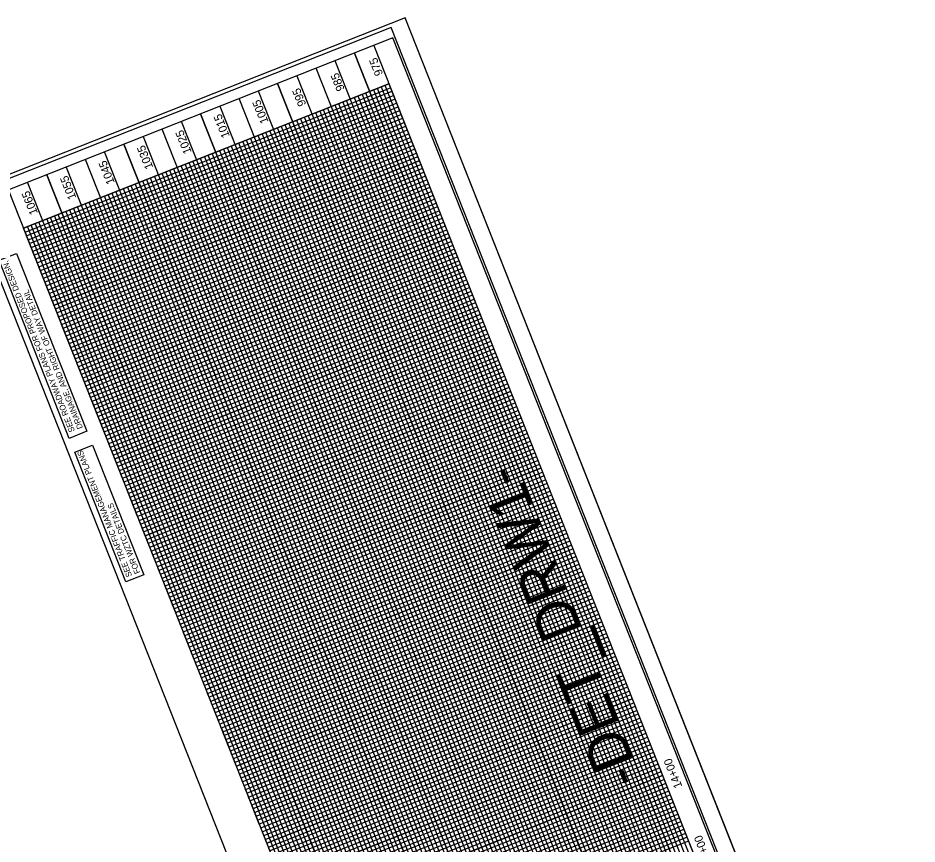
# Model space of a CAD drawing. Extents: x 1250120 to 1251758, y 748130 to 750098.
# Drawn here: x 1250670 to 1251758, y 749099 to 750098 of the extents above; entities that cross this region are included whole.
import ezdxf

# ---------------------------------------------------------------- set-up
doc = ezdxf.new("R2010")
doc.units = 0
for name, color, linetype in [('Exist Vertical Profile Horizontal Axis Label Major', 7, 'Continuous'), ('Exist Vertical Profile Vertical Axis Label', 7, 'Continuous'), ('Prop Grid Mask', 7, 'Continuous'), ('Prop PFL Text', 7, 'Continuous'), ('Sheet Cutting Line CELL', 7, 'Continuous'), ('Sheet Data Field CELL', 7, 'Continuous'), ('Sheet DOT Grid CELL', 7, 'Continuous'), ('Sheet Layout Plan Border', 7, 'Continuous'), ('Sheet Layout Profile Border Port 2', 7, 'Continuous'), ('Sheet Plan And Profile CELL', 7, 'Continuous'), ('Sheet Plot Border Inside CELL', 7, 'Continuous'), ('Sheet Plot Border Outside CELL', 7, 'Continuous'), ('Sheet Profile Grid Major CELL', 7, 'Continuous'), ('Sheet Profile Grid Middle CELL', 7, 'Continuous'), ('Sheet Profile Grid Minor CELL', 7, 'Continuous')]:
    doc.layers.add(name, color=color, linetype=linetype)

msp = doc.modelspace()

# ---------------------------------------------------------------- linework, layer by layer
at = {"layer": 'Prop Grid Mask'}
for points in [[(1250732.4, 749589.4), (1250647.3, 749804.8), (1250668.7, 749813.2), (1250753.8, 749597.9)], [(1250801.1, 749415.8), (1250739.1, 749572.6), (1250760.5, 749581), (1250822.5, 749424.3)]]:
    msp.add_lwpolyline(points, close=True, dxfattribs=at)
at = {"layer": 'Sheet Cutting Line CELL'}
msp.add_line((1251757.6, 748532.4), (1251138.6, 750098), dxfattribs=at)
at = {"layer": 'Sheet DOT Grid CELL'}
for p, q in [((1251629, 748660.6), (1251077.4, 750055.5)), ((1251582.5, 748642.2), (1251030.9, 750037.1)), ((1250677.3, 749843.5), (1251119.1, 750018.2)), ((1251536, 748623.8), (1250984.4, 750018.7)), ((1251489.5, 748605.4), (1250937.9, 750000.4)), ((1251443, 748587.1), (1250891.4, 749982)), ((1250695.7, 749797.1), (1251137.5, 749971.7)), ((1251396.5, 748568.7), (1250844.9, 749963.6)), ((1251350, 748550.3), (1250798.5, 749945.2)), ((1250714.1, 749750.6), (1251155.8, 749925.2)), ((1251303.5, 748531.9), (1250752, 749926.8)), ((1251257, 748513.5), (1250705.5, 749908.4)), ((1251210.5, 748495.1), (1250659, 749890)), ((1250732.5, 749704.1), (1251174.2, 749878.7)), ((1250750.9, 749657.6), (1251192.6, 749832.2)), ((1250769.3, 749611.1), (1251211, 749785.7)), ((1250787.7, 749564.6), (1251229.4, 749739.2)), ((1250806, 749518.1), (1251247.8, 749692.7)), ((1250824.4, 749471.6), (1251266.1, 749646.2)), ((1250842.8, 749425.1), (1251284.5, 749599.7)), ((1250861.2, 749378.6), (1251302.9, 749553.2)), ((1250879.6, 749332.1), (1251321.3, 749506.7)), ((1250898, 749285.6), (1251339.7, 749460.2)), ((1250916.4, 749239.1), (1251358.1, 749413.7)), ((1250934.7, 749192.6), (1251376.5, 749367.3)), ((1250953.1, 749146.1), (1251394.8, 749320.8)), ((1250971.5, 749099.6), (1251413.2, 749274.3)), ((1250989.9, 749053.1), (1251431.6, 749227.8)), ((1251008.3, 749006.6), (1251450, 749181.3)), ((1251026.7, 748960.1), (1251468.4, 749134.8))]:
    msp.add_line(p, q, dxfattribs=at)
at = {"layer": 'Sheet Layout Plan Border'}
msp.add_lwpolyline([(1251145.6, 748523.2), (1250727.2, 748357.8), (1250285.9, 749473.7), (1250436.1, 749533), (1250362.5, 749719.1), (1250630.8, 749825.2)], close=True, dxfattribs=at)
at = {"layer": 'Sheet Layout Profile Border Port 2'}
msp.add_lwpolyline([(1251192.1, 748541.6), (1250677.3, 749843.5), (1251119.1, 750018.2), (1251633.9, 748716.3)], close=True, dxfattribs=at)
at = {"layer": 'Sheet Plan And Profile CELL'}
msp.add_line((1251100.7, 750064.7), (1251652.2, 748669.8), dxfattribs=at)
msp.add_lwpolyline([(1250147.5, 749687.8), (1250699.1, 748292.9), (1251675.5, 748679), (1251123.9, 750073.9)], close=True, dxfattribs=at)
at = {"layer": 'Sheet Plot Border Inside CELL'}
msp.add_lwpolyline([(1251734.3, 748537.2), (1251121.7, 750086.4), (1250140.6, 749698.5), (1250753.2, 748149.2)], close=True, dxfattribs=at)
at = {"layer": 'Sheet Plot Border Outside CELL'}
msp.add_lwpolyline([(1251757.6, 748532.4), (1251138.6, 750098), (1250120.3, 749695.3), (1250739.4, 748129.8)], close=True, dxfattribs=at)
at = {"layer": 'Sheet Profile Grid Major CELL'}
for points in [[(1251077.4, 750055.5), (1251629, 748660.6)], [(1250984.4, 750018.7), (1251536, 748623.8), (1251582.5, 748642.2), (1251030.9, 750037.1)], [(1251119.1, 750018.2), (1250677.3, 749843.5)], [(1250891.4, 749982), (1251443, 748587.1), (1251489.5, 748605.4), (1250937.9, 750000.4)], [(1251155.8, 749925.2), (1250714.1, 749750.6), (1250695.7, 749797.1), (1251137.5, 749971.7)], [(1250798.5, 749945.2), (1251350, 748550.3), (1251396.5, 748568.7), (1250844.9, 749963.6)], [(1250705.5, 749908.4), (1251257, 748513.5), (1251303.5, 748531.9), (1250752, 749926.8)], [(1251210.5, 748495.1), (1250659, 749890)], [(1251192.6, 749832.2), (1250750.9, 749657.6), (1250732.5, 749704.1), (1251174.2, 749878.7)], [(1251229.4, 749739.2), (1250787.7, 749564.6), (1250769.3, 749611.1), (1251211, 749785.7)], [(1251266.1, 749646.2), (1250824.4, 749471.6), (1250806, 749518.1), (1251247.8, 749692.7)], [(1251302.9, 749553.2), (1250861.2, 749378.6), (1250842.8, 749425.1), (1251284.5, 749599.7)], [(1251339.7, 749460.2), (1250898, 749285.6), (1250879.6, 749332.1), (1251321.3, 749506.7)], [(1251376.5, 749367.3), (1250934.7, 749192.6), (1250916.4, 749239.1), (1251358.1, 749413.7)], [(1251413.2, 749274.3), (1250971.5, 749099.6), (1250953.1, 749146.1), (1251394.8, 749320.8)], [(1251450, 749181.3), (1251008.3, 749006.6), (1250989.9, 749053.1), (1251431.6, 749227.8)], [(1251486.8, 749088.3), (1251045.1, 748913.6), (1251026.7, 748960.1), (1251468.4, 749134.8)]]:
    msp.add_lwpolyline(points, dxfattribs=at)
at = {"layer": 'Sheet Profile Grid Middle CELL'}
for p, q in [((1251605.7, 748651.4), (1251054.2, 750046.3)), ((1251007.7, 750027.9), (1251559.2, 748633)), ((1251512.8, 748614.6), (1250961.2, 750009.6)), ((1250914.7, 749991.2), (1251466.3, 748596.3)), ((1251419.8, 748577.9), (1250868.2, 749972.8)), ((1250821.7, 749954.4), (1251373.3, 748559.5)), ((1251326.8, 748541.1), (1250775.2, 749936)), ((1250728.7, 749917.6), (1251280.3, 748522.7)), ((1251233.8, 748504.3), (1250682.2, 749899.2))]:
    msp.add_line(p, q, dxfattribs=at)
for points in [[(1251146.6, 749948.5), (1250704.9, 749773.8), (1250686.5, 749820.3), (1251128.3, 749995)], [(1251183.4, 749855.5), (1250741.7, 749680.8), (1250723.3, 749727.3), (1251165, 749902)], [(1251220.2, 749762.5), (1250778.5, 749587.8), (1250760.1, 749634.3), (1251201.8, 749809)], [(1251257, 749669.5), (1250815.2, 749494.8), (1250796.8, 749541.3), (1251238.6, 749716)], [(1251293.7, 749576.5), (1250852, 749401.8), (1250833.6, 749448.3), (1251275.3, 749623)], [(1251330.5, 749483.5), (1250888.8, 749308.8), (1250870.4, 749355.3), (1251312.1, 749530)], [(1251367.3, 749390.5), (1250925.5, 749215.8), (1250907.2, 749262.3), (1251348.9, 749437)], [(1251404, 749297.5), (1250962.3, 749122.8), (1250943.9, 749169.3), (1251385.7, 749344)], [(1251440.8, 749204.5), (1250999.1, 749029.9), (1250980.7, 749076.3), (1251422.4, 749251)], [(1251477.6, 749111.5), (1251035.9, 748936.9), (1251017.5, 748983.4), (1251459.2, 749158)]]:
    msp.add_lwpolyline(points, dxfattribs=at)
at = {"layer": 'Sheet Profile Grid Minor CELL'}
for points in [[(1251122.7, 750008.9), (1250681, 749834.3), (1250679.2, 749838.9), (1251120.9, 750013.6)], [(1251629.2, 748714.5), (1251114.4, 750016.4), (1251109.8, 750014.5), (1251624.6, 748712.6), (1251619.9, 748710.8), (1251105.1, 750012.7), (1251100.5, 750010.9), (1251615.3, 748708.9), (1251610.6, 748707.1), (1251606, 748705.3), (1251091.2, 750007.2), (1251086.5, 750005.3), (1251601.3, 748703.4), (1251596.7, 748701.6), (1251081.9, 750003.5), (1251077.2, 750001.7), (1251592, 748699.7), (1251587.4, 748697.9), (1251582.7, 748696.1), (1251067.9, 749998), (1251063.3, 749996.1), (1251578.1, 748694.2), (1251573.4, 748692.4), (1251058.6, 749994.3)], [(1251126.4, 749999.6), (1250684.7, 749825), (1250682.9, 749829.6), (1251124.6, 750004.3)], [(1251131.9, 749985.7), (1250690.2, 749811), (1250688.4, 749815.7), (1251130.1, 749990.3)], [(1251568.8, 748690.6), (1251054, 749992.5), (1251044.7, 749988.8), (1251559.5, 748686.9)], [(1251135.6, 749976.4), (1250693.9, 749801.7), (1250692.1, 749806.4), (1251133.8, 749981)], [(1251531.6, 748675.8), (1251016.8, 749977.8), (1251012.1, 749975.9), (1251526.9, 748674)], [(1251545.5, 748681.4), (1251030.7, 749983.3), (1251021.4, 749979.6), (1251536.2, 748677.7)], [(1251554.8, 748685), (1251040, 749987), (1251035.4, 749985.1), (1251550.2, 748683.2)], [(1251141.1, 749962.4), (1250699.4, 749787.8), (1250697.6, 749792.4), (1251139.3, 749967.1)], [(1251508.3, 748666.7), (1250993.5, 749968.6), (1250988.9, 749966.7), (1251503.7, 748664.8)], [(1251522.3, 748672.2), (1251007.5, 749974.1), (1250998.2, 749970.4), (1251513, 748668.5)], [(1251144.8, 749953.1), (1250703.1, 749778.5), (1250701.2, 749783.1), (1251143, 749957.8)], [(1251475.8, 748653.8), (1250961, 749955.7), (1250951.7, 749952), (1251466.5, 748650.1)], [(1251485.1, 748657.5), (1250970.3, 749959.4), (1250965.6, 749957.5), (1251480.4, 748655.6)], [(1251499, 748663), (1250984.2, 749964.9), (1250974.9, 749961.2), (1251489.7, 748659.3)], [(1251452.5, 748644.6), (1250937.7, 749946.5), (1250928.4, 749942.8), (1251443.2, 748640.9)], [(1251461.8, 748648.3), (1250947, 749950.2), (1250942.4, 749948.3), (1251457.2, 748646.4)], [(1251150.3, 749939.2), (1250708.6, 749764.5), (1250706.8, 749769.2), (1251148.5, 749943.8)], [(1251154, 749929.9), (1250712.3, 749755.2), (1250710.4, 749759.9), (1251152.2, 749934.5)], [(1251429.3, 748635.4), (1250914.5, 749937.3), (1250905.2, 749933.6), (1251420, 748631.7)], [(1251438.6, 748639.1), (1250923.8, 749941), (1250919.1, 749939.2), (1251433.9, 748637.2)], [(1251406, 748626.2), (1250891.2, 749928.1), (1250881.9, 749924.4), (1251396.7, 748622.5)], [(1251415.3, 748629.9), (1250900.5, 749931.8), (1250895.9, 749930), (1251410.7, 748628)], [(1251159.5, 749915.9), (1250717.8, 749741.3), (1250716, 749745.9), (1251157.7, 749920.6)], [(1251368.8, 748611.5), (1250854, 749913.4), (1250849.4, 749911.6), (1251364.2, 748609.7)], [(1251382.8, 748617), (1250868, 749918.9), (1250858.7, 749915.3), (1251373.5, 748613.3)], [(1251392.1, 748620.7), (1250877.3, 749922.6), (1250872.6, 749920.8), (1251387.4, 748618.9)], [(1251163.2, 749906.6), (1250721.5, 749732), (1250719.6, 749736.6), (1251161.4, 749911.3)], [(1251345.6, 748602.3), (1250830.8, 749904.2), (1250826.1, 749902.4), (1251340.9, 748600.5)], [(1251359.5, 748607.8), (1250844.7, 749909.7), (1250835.4, 749906.1), (1251350.2, 748604.1)], [(1251168.7, 749892.7), (1250727, 749718), (1250725.1, 749722.7), (1251166.9, 749897.3)], [(1251313, 748589.4), (1250798.2, 749891.4), (1250788.9, 749887.7), (1251303.7, 748585.8)], [(1251322.3, 748593.1), (1250807.5, 749895), (1250802.9, 749893.2), (1251317.7, 748591.3)], [(1251336.3, 748598.6), (1250821.5, 749900.5), (1250812.2, 749896.9), (1251327, 748594.9)], [(1251172.4, 749883.4), (1250730.7, 749708.7), (1250728.8, 749713.4), (1251170.5, 749888)], [(1251289.8, 748580.2), (1250775, 749882.2)], [(1251299.1, 748583.9), (1250784.3, 749885.8), (1250779.6, 749884), (1251294.4, 748582.1)], [(1251177.9, 749869.4), (1250736.2, 749694.8), (1250734.3, 749699.4), (1251176.1, 749874.1)], [(1251257.2, 748567.4), (1250742.4, 749869.3), (1250737.8, 749867.5), (1251252.6, 748565.5)], [(1251271.2, 748572.9), (1250756.4, 749874.8), (1250751.7, 749873), (1251266.5, 748571)], [(1251280.5, 748576.6), (1250765.7, 749878.5), (1250761, 749876.6), (1251275.8, 748574.7)], [(1251234, 748558.2), (1250719.2, 749860.1), (1250714.5, 749858.3), (1251229.3, 748556.3)], [(1251247.9, 748563.7), (1250733.1, 749865.6), (1250728.5, 749863.8), (1251243.3, 748561.9)], [(1251181.6, 749860.1), (1250739.9, 749685.5), (1250738, 749690.1), (1251179.7, 749864.8)], [(1251201.4, 748545.3), (1250686.6, 749847.2), (1250682, 749845.4), (1251196.8, 748543.5)], [(1251210.7, 748549), (1250695.9, 749850.9), (1250691.3, 749849.1), (1251206.1, 748547.1)], [(1251224.7, 748554.5), (1250709.9, 749856.4), (1250705.2, 749854.6), (1251220, 748552.7)], [(1251187.1, 749846.2), (1250745.4, 749671.5), (1250743.5, 749676.2), (1251185.3, 749850.8)], [(1251190.8, 749836.9), (1250749, 749662.2), (1250747.2, 749666.9), (1251188.9, 749841.5)], [(1251196.3, 749822.9), (1250754.6, 749648.3), (1250752.7, 749652.9), (1251194.4, 749827.6)], [(1251200, 749813.6), (1250758.2, 749639), (1250756.4, 749643.6), (1251198.1, 749818.3)], [(1251205.5, 749799.7), (1250763.8, 749625), (1250761.9, 749629.7), (1251203.6, 749804.3)], [(1251209.2, 749790.4), (1250767.4, 749615.7), (1250765.6, 749620.4), (1251207.3, 749795)], [(1251214.7, 749776.4), (1250772.9, 749601.8), (1250771.1, 749606.4), (1251212.8, 749781.1)], [(1251218.3, 749767.1), (1250776.6, 749592.5), (1250774.8, 749597.1), (1251216.5, 749771.8)], [(1251223.9, 749753.2), (1250782.1, 749578.5), (1250780.3, 749583.2), (1251222, 749757.8)], [(1251227.5, 749743.9), (1250785.8, 749569.2), (1250784, 749573.9), (1251225.7, 749748.5)], [(1251233.1, 749729.9), (1250791.3, 749555.3), (1250789.5, 749559.9), (1251231.2, 749734.6)], [(1251236.7, 749720.6), (1250795, 749546), (1250793.2, 749550.6), (1251234.9, 749725.3)], [(1251242.2, 749706.7), (1250800.5, 749532), (1250798.7, 749536.7), (1251240.4, 749711.3)], [(1251245.9, 749697.4), (1250804.2, 749522.7), (1250802.4, 749527.4), (1251244.1, 749702)], [(1251251.4, 749683.4), (1250809.7, 749508.8), (1250807.9, 749513.4), (1251249.6, 749688.1)], [(1251255.1, 749674.1), (1250813.4, 749499.5), (1250811.6, 749504.1), (1251253.3, 749678.8)], [(1251260.6, 749660.2), (1250818.9, 749485.5), (1250817.1, 749490.2), (1251258.8, 749664.8)], [(1251264.3, 749650.9), (1250822.6, 749476.2), (1250820.8, 749480.9), (1251262.5, 749655.5)], [(1251269.8, 749636.9), (1250828.1, 749462.3), (1250826.3, 749466.9), (1251268, 749641.6)], [(1251273.5, 749627.6), (1250831.8, 749453), (1250829.9, 749457.6), (1251271.7, 749632.3)], [(1251279, 749613.7), (1250837.3, 749439), (1250835.5, 749443.7), (1251277.2, 749618.3)], [(1251282.7, 749604.4), (1250841, 749429.7), (1250839.1, 749434.4), (1251280.9, 749609)], [(1251288.2, 749590.4), (1250846.5, 749415.8), (1250844.7, 749420.4), (1251286.4, 749595.1)], [(1251291.9, 749581.1), (1250850.2, 749406.5), (1250848.3, 749411.1), (1251290.1, 749585.8)], [(1251297.4, 749567.2), (1250855.7, 749392.5), (1250853.8, 749397.2), (1251295.6, 749571.8)], [(1251301.1, 749557.9), (1250859.4, 749383.2), (1250857.5, 749387.9), (1251299.2, 749562.5)], [(1251306.6, 749543.9), (1250864.9, 749369.3), (1250863, 749373.9), (1251304.8, 749548.6)], [(1251310.3, 749534.6), (1250868.6, 749360), (1250866.7, 749364.6), (1251308.4, 749539.3)], [(1251315.8, 749520.7), (1250874.1, 749346), (1250872.2, 749350.7), (1251314, 749525.3)], [(1251319.5, 749511.4), (1250877.7, 749336.7), (1250875.9, 749341.4), (1251317.6, 749516)], [(1251325, 749497.4), (1250883.3, 749322.8), (1250881.4, 749327.4), (1251323.1, 749502.1)], [(1251328.7, 749488.1), (1250886.9, 749313.5), (1250885.1, 749318.1), (1251326.8, 749492.8)], [(1251334.2, 749474.2), (1250892.5, 749299.5), (1250890.6, 749304.2), (1251332.3, 749478.8)], [(1251337.9, 749464.9), (1250896.1, 749290.2), (1250894.3, 749294.9), (1251336, 749469.5)], [(1251343.4, 749450.9), (1250901.6, 749276.3), (1250899.8, 749280.9), (1251341.5, 749455.6)], [(1251347, 749441.6), (1250905.3, 749267), (1250903.5, 749271.6), (1251345.2, 749446.3)], [(1251352.6, 749427.7), (1250910.8, 749253), (1250909, 749257.7), (1251350.7, 749432.3)], [(1251356.2, 749418.4), (1250914.5, 749243.7), (1250912.7, 749248.4), (1251354.4, 749423)], [(1251361.8, 749404.4), (1250920, 749229.8), (1250918.2, 749234.4), (1251359.9, 749409.1)], [(1251365.4, 749395.2), (1250923.7, 749220.5), (1250921.9, 749225.1), (1251363.6, 749399.8)], [(1251370.9, 749381.2), (1250929.2, 749206.5), (1250927.4, 749211.2), (1251369.1, 749385.9)], [(1251374.6, 749371.9), (1250932.9, 749197.2), (1250931.1, 749201.9), (1251372.8, 749376.6)], [(1251380.1, 749358), (1250938.4, 749183.3), (1250936.6, 749187.9), (1251378.3, 749362.6)], [(1251383.8, 749348.7), (1250942.1, 749174), (1250940.3, 749178.6), (1251382, 749353.3)], [(1251389.3, 749334.7), (1250947.6, 749160), (1250945.8, 749164.7), (1251387.5, 749339.4)], [(1251393, 749325.4), (1250951.3, 749150.7), (1250949.4, 749155.4), (1251391.2, 749330.1)], [(1251398.5, 749311.5), (1250956.8, 749136.8), (1250955, 749141.4), (1251396.7, 749316.1)], [(1251402.2, 749302.2), (1250960.5, 749127.5), (1250958.6, 749132.1), (1251400.4, 749306.8)], [(1251407.7, 749288.2), (1250966, 749113.5), (1250964.2, 749118.2), (1251405.9, 749292.9)], [(1251411.4, 749278.9), (1250969.7, 749104.2), (1250967.8, 749108.9), (1251409.6, 749283.6)], [(1251416.9, 749265), (1250975.2, 749090.3), (1250973.3, 749094.9), (1251415.1, 749269.6)], [(1251420.6, 749255.7), (1250978.9, 749081), (1250977, 749085.6), (1251418.7, 749260.3)], [(1251426.1, 749241.7), (1250984.4, 749067), (1250982.5, 749071.7), (1251424.3, 749246.4)], [(1251429.8, 749232.4), (1250988.1, 749057.7), (1250986.2, 749062.4), (1251427.9, 749237.1)], [(1251435.3, 749218.5), (1250993.6, 749043.8), (1250991.7, 749048.4), (1251433.5, 749223.1)], [(1251439, 749209.2), (1250997.3, 749034.5), (1250995.4, 749039.2), (1251437.1, 749213.8)], [(1251444.5, 749195.2), (1251002.8, 749020.6), (1251000.9, 749025.2), (1251442.6, 749199.9)], [(1251448.2, 749185.9), (1251006.4, 749011.3), (1251004.6, 749015.9), (1251446.3, 749190.6)], [(1251453.7, 749172), (1251012, 748997.3), (1251010.1, 749002), (1251451.8, 749176.6)], [(1251457.4, 749162.7), (1251015.6, 748988), (1251013.8, 748992.7), (1251455.5, 749167.3)], [(1251462.9, 749148.7), (1251021.2, 748974.1), (1251019.3, 748978.7), (1251461, 749153.4)], [(1251466.6, 749139.4), (1251024.8, 748964.8), (1251023, 748969.4), (1251464.7, 749144.1)], [(1251472.1, 749125.5), (1251030.3, 748950.8), (1251028.5, 748955.5), (1251470.2, 749130.1)], [(1251475.7, 749116.2), (1251034, 748941.5), (1251032.2, 748946.2), (1251473.9, 749120.8)], [(1251481.3, 749102.2), (1251039.5, 748927.6), (1251037.7, 748932.2), (1251479.4, 749106.9)]]:
    msp.add_lwpolyline(points, dxfattribs=at)

# ---------------------------------------------------------------- texts
at = {"layer": 'Exist Vertical Profile Horizontal Axis Label Major'}
for s, p in [('14+00', (1251474, 749168.3)), ('13+00', (1251510.7, 749075.3))]:
    msp.add_text(s, height=10, rotation=111.5743, dxfattribs=at).set_placement(p)
at = {"layer": 'Exist Vertical Profile Vertical Axis Label'}
for s, p in [('975', (1251112.2, 750030.2)), ('985', (1251065.7, 750011.8)), ('995', (1251019.2, 749993.4)), ('1005', (1250973.7, 749972.4)), ('1015', (1250926.8, 749955.2)), ('1025', (1250880.7, 749935.7)), ('1035', (1250834.2, 749917.3)), ('1045', (1250787.7, 749898.9)), ('1055', (1250741.2, 749880.5)), ('1065', (1250694.7, 749862.1))]:
    msp.add_text(s, height=10, rotation=111.5743, dxfattribs=at).set_placement(p)
at = {"layer": 'Prop PFL Text'}
for s, p in [('SEE ROADWAY PLANS FOR PROPOSED DESIGN, ', (1250739.4, 749598.4)), ('DRAINAGE, AND RIGHT OF WAY DETAIL', (1250749.1, 749602.2)), ('SEE TRAFFIC MANAGEMENT PLANS ', (1250808.6, 749423.2)), ('FOR WZTC DETAILS', (1250818.4, 749427.1))]:
    msp.add_text(s, height=7, rotation=111.5743, dxfattribs=at).set_placement(p)
at = {"layer": 'Sheet Data Field CELL'}
msp.add_text('-DET_DRW1-', height=50, rotation=111.5743, dxfattribs=at).set_placement((1251424.7, 749177.2))

doc.saveas('drawing.dxf')
